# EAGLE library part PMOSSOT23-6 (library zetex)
MOS FET
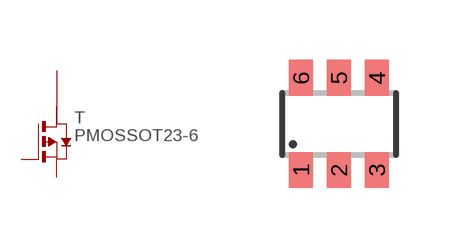
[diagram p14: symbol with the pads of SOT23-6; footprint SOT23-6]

Designator prefix T

## PMOSSOT23-6 (OC_FARNELL: unknown; OC_NEWARK: unknown)  [SOT23-6]
1  D  pas
2  D1  pas
3  S  pas
4  G  pas
5  D2  pas
6  D3  pas

## Footprint SOT23-6 (pad centres in mm)
Small Outline Transistor 6 lead
smd 0.6 x 0.9: 1 -0.95,-1.15; 2 0,-1.15; 3 0.95,-1.15; 4 0.95,1.15; 5 0,1.15; 6 -0.95,1.15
